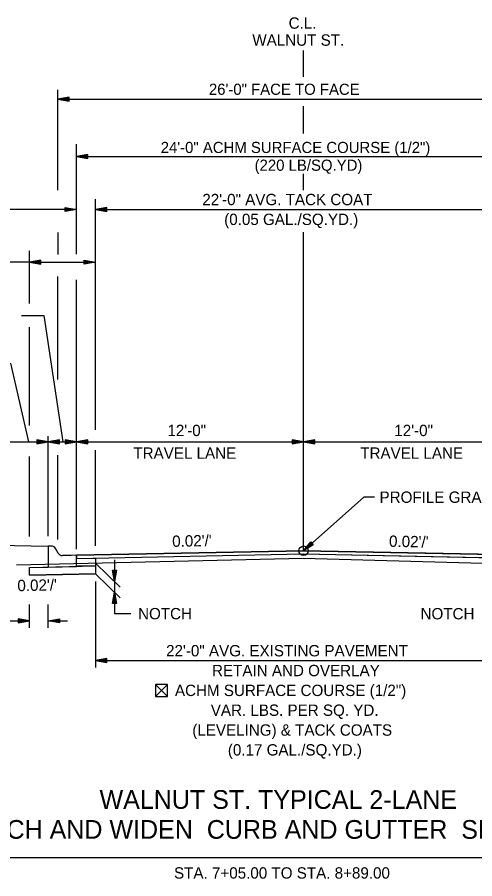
# Model space of a CAD drawing. Extents: x 1001270 to 1003428, y 1840152 to 1842912.
# Drawn here: x 1001337.71 to 1001361.9, y 1840763.76 to 1840809.37 of the extents above; entities that cross this region are included whole.
import ezdxf

# ---------------------------------------------------------------- set-up
doc = ezdxf.new("R2010")
doc.units = 0
doc.layers.add('10', color=7, linetype='Continuous')
doc.layers.add('19', color=7, linetype='Continuous')

msp = doc.modelspace()

# ---------------------------------------------------------------- linework, layer by layer
at = {"layer": '10'}
for p, q in [((1001345.013, 1840774.048), (1001345.654, 1840773.407)), ((1001345.654, 1840774.048), (1001345.013, 1840773.407)), ((1001345.394, 1840773.407), (1001345.405, 1840773.407))]:
    msp.add_line(p, q, dxfattribs=at)
msp.add_lwpolyline([(1001345.405, 1840773.407), (1001345.654, 1840773.407), (1001345.654, 1840774.048), (1001345.013, 1840774.048), (1001345.013, 1840773.407), (1001345.394, 1840773.407)], dxfattribs=at)
at = {"layer": '19'}
for p, q in [((1001352.846, 1840806.222), (1001352.846, 1840807.614)), ((1001339.847, 1840800.22), (1001339.847, 1840805.535)), ((1001340.447, 1840805.137), (1001339.847, 1840805.032)), ((1001339.847, 1840805.032), (1001365.85, 1840805.032)), ((1001339.847, 1840805.032), (1001340.447, 1840804.927)), ((1001340.447, 1840805.082), (1001340.007, 1840805.047)), ((1001340.007, 1840805.017), (1001340.447, 1840804.977)), ((1001340.447, 1840804.927), (1001340.447, 1840805.137)), ((1001352.846, 1840803.218), (1001352.846, 1840804.663)), ((1001340.846, 1840796.831), (1001340.846, 1840802.657)), ((1001341.447, 1840802.11), (1001340.847, 1840802.005)), ((1001341.447, 1840802.055), (1001341.007, 1840802.02)), ((1001341.447, 1840801.9), (1001341.447, 1840802.11)), ((1001340.846, 1840802.005), (1001364.849, 1840802.005)), ((1001340.847, 1840802.005), (1001341.447, 1840801.9)), ((1001341.007, 1840801.99), (1001341.447, 1840801.95)), ((1001352.846, 1840800.214), (1001352.846, 1840801.087)), ((1001340.245, 1840799.094), (1001340.245, 1840799.304)), ((1001340.245, 1840799.304), (1001340.845, 1840799.199)), ((1001341.846, 1840787.532), (1001341.846, 1840799.731)), ((1001342.446, 1840799.304), (1001341.846, 1840799.199)), ((1001342.446, 1840799.094), (1001342.446, 1840799.304)), ((1001340.845, 1840799.199), (1001324.293, 1840799.199)), ((1001340.245, 1840799.249), (1001340.685, 1840799.214)), ((1001340.845, 1840799.199), (1001340.245, 1840799.094)), ((1001340.685, 1840799.184), (1001340.245, 1840799.144)), ((1001340.852, 1840799.198), (1001340.846, 1840799.198)), ((1001341.846, 1840799.199), (1001342.446, 1840799.094)), ((1001341.846, 1840799.199), (1001363.846, 1840799.199)), ((1001342.446, 1840799.249), (1001342.006, 1840799.214)), ((1001342.006, 1840799.184), (1001342.446, 1840799.144)), ((1001339.846, 1840797.981), (1001339.846, 1840796.814)), ((1001352.846, 1840781.126), (1001352.846, 1840797.995)), ((1001338.346, 1840794.208), (1001338.346, 1840796.999)), ((1001338.346, 1840796.399), (1001323.169, 1840796.399)), ((1001338.946, 1840796.504), (1001338.346, 1840796.399)), ((1001338.346, 1840796.399), (1001338.946, 1840796.294)), ((1001338.346, 1840796.399), (1001341.846, 1840796.399)), ((1001338.946, 1840796.449), (1001338.506, 1840796.414)), ((1001338.506, 1840796.384), (1001338.946, 1840796.344)), ((1001338.946, 1840796.294), (1001338.946, 1840796.504)), ((1001341.246, 1840796.294), (1001341.246, 1840796.504)), ((1001341.246, 1840796.504), (1001341.846, 1840796.399)), ((1001341.246, 1840796.449), (1001341.686, 1840796.414)), ((1001341.846, 1840796.399), (1001341.246, 1840796.294)), ((1001341.686, 1840796.384), (1001341.246, 1840796.344)), ((1001339.846, 1840790.194), (1001339.846, 1840795.639)), ((1001340.846, 1840781.214), (1001340.846, 1840795.465)), ((1001337.926, 1840793.587), (1001339.105, 1840793.587)), ((1001339.105, 1840793.587), (1001340.12, 1840786.895)), ((1001338.346, 1840787.749), (1001338.346, 1840792.965)), ((1001337.341, 1840791.052), (1001338.298, 1840786.895)), ((1001338.746, 1840787), (1001338.746, 1840786.79)), ((1001339.346, 1840786.895), (1001338.746, 1840787)), ((1001339.346, 1840781.905), (1001339.346, 1840787.195)), ((1001339.946, 1840787), (1001339.346, 1840786.895)), ((1001339.946, 1840786.79), (1001339.946, 1840787)), ((1001340.246, 1840787), (1001340.246, 1840786.79)), ((1001340.846, 1840786.895), (1001340.246, 1840787)), ((1001341.446, 1840787), (1001340.846, 1840786.895)), ((1001341.446, 1840786.79), (1001341.446, 1840787)), ((1001352.246, 1840787), (1001352.246, 1840786.79)), ((1001352.846, 1840786.895), (1001352.246, 1840787)), ((1001353.446, 1840787), (1001352.846, 1840786.895)), ((1001353.446, 1840786.79), (1001353.446, 1840787)), ((1001331.346, 1840786.895), (1001340.846, 1840786.895)), ((1001339.186, 1840786.91), (1001338.746, 1840786.945)), ((1001338.746, 1840786.79), (1001339.346, 1840786.895)), ((1001338.746, 1840786.84), (1001339.186, 1840786.88)), ((1001339.346, 1840786.895), (1001339.946, 1840786.79)), ((1001339.946, 1840786.945), (1001339.506, 1840786.91)), ((1001339.506, 1840786.88), (1001339.946, 1840786.84)), ((1001340.686, 1840786.91), (1001340.246, 1840786.945)), ((1001340.246, 1840786.79), (1001340.846, 1840786.895)), ((1001340.246, 1840786.84), (1001340.686, 1840786.88)), ((1001340.846, 1840786.895), (1001352.846, 1840786.895)), ((1001340.846, 1840786.895), (1001341.446, 1840786.79)), ((1001341.446, 1840786.945), (1001341.006, 1840786.91)), ((1001341.006, 1840786.88), (1001341.446, 1840786.84)), ((1001352.686, 1840786.91), (1001352.246, 1840786.945)), ((1001352.246, 1840786.79), (1001352.846, 1840786.895)), ((1001352.246, 1840786.84), (1001352.686, 1840786.88)), ((1001352.846, 1840786.895), (1001364.846, 1840786.895)), ((1001352.846, 1840786.895), (1001353.446, 1840786.79)), ((1001353.446, 1840786.945), (1001353.006, 1840786.91)), ((1001353.006, 1840786.88), (1001353.446, 1840786.84)), ((1001338.346, 1840781.88), (1001338.346, 1840786.119)), ((1001339.846, 1840781.717), (1001339.846, 1840786.184)), ((1001341.846, 1840781.391), (1001341.846, 1840786.445)), ((1001352.846, 1840781.126), (1001353.225, 1840781.603)), ((1001352.957, 1840781.239), (1001353.257, 1840781.559)), ((1001353.225, 1840781.603), (1001353.363, 1840781.446)), ((1001336.338, 1840781.432), (1001339.336, 1840781.371)), ((1001339.512, 1840781.371), (1001339.346, 1840781.371)), ((1001339.346, 1840781.371), (1001339.346, 1840781.038)), ((1001339.346, 1840781.038), (1001339.346, 1840780.856)), ((1001339.875, 1840780.996), (1001339.729, 1840781.247)), ((1001340.846, 1840780.886), (1001352.846, 1840781.126)), ((1001353.363, 1840781.446), (1001352.846, 1840781.126)), ((1001352.846, 1840781.126), (1001364.846, 1840780.886)), ((1001353.33, 1840781.478), (1001352.976, 1840781.222)), ((1001339.346, 1840780.856), (1001339.346, 1840780.263)), ((1001340.562, 1840780.881), (1001340.096, 1840780.871)), ((1001340.846, 1840780.886), (1001340.562, 1840780.881)), ((1001340.562, 1840780.881), (1001340.562, 1840780.88)), ((1001340.562, 1840780.88), (1001340.562, 1840780.881)), ((1001340.846, 1840780.72), (1001352.846, 1840780.96)), ((1001340.846, 1840780.72), (1001341.846, 1840780.74)), ((1001340.846, 1840780.303), (1001340.846, 1840780.72)), ((1001341.846, 1840780.74), (1001341.846, 1840779.912)), ((1001341.846, 1840780.74), (1001341.846, 1840780.323)), ((1001352.846, 1840780.96), (1001364.846, 1840780.72)), ((1001338.346, 1840780.243), (1001341.846, 1840780.323)), ((1001338.346, 1840780.243), (1001339.346, 1840780.263)), ((1001338.346, 1840779.836), (1001338.346, 1840780.243)), ((1001338.346, 1840779.836), (1001338.346, 1840780.243)), ((1001338.346, 1840780.243), (1001338.346, 1840780.243)), ((1001339.346, 1840780.263), (1001340.846, 1840780.294)), ((1001340.846, 1840780.303), (1001341.846, 1840780.323)), ((1001341.846, 1840780.323), (1001340.846, 1840780.303)), ((1001340.846, 1840780.303), (1001340.846, 1840780.303)), ((1001341.846, 1840780.474), (1001343.146, 1840779.201)), ((1001341.846, 1840780.323), (1001341.846, 1840779.903)), ((1001338.346, 1840779.836), (1001341.846, 1840779.906)), ((1001341.846, 1840779.903), (1001338.346, 1840779.836)), ((1001341.846, 1840779.906), (1001343.146, 1840778.634)), ((1001342.741, 1840780.095), (1001342.951, 1840780.095)), ((1001342.846, 1840779.495), (1001342.741, 1840780.095)), ((1001342.831, 1840779.655), (1001342.791, 1840780.095)), ((1001342.951, 1840780.095), (1001342.846, 1840779.495)), ((1001342.896, 1840780.095), (1001342.861, 1840779.655)), ((1001341.846, 1840779.505), (1001341.846, 1840774.942)), ((1001342.741, 1840778.327), (1001342.846, 1840778.927)), ((1001342.796, 1840778.327), (1001342.831, 1840778.767)), ((1001342.846, 1840778.927), (1001342.951, 1840778.327)), ((1001342.861, 1840778.767), (1001342.901, 1840778.327)), ((1001342.951, 1840778.327), (1001342.741, 1840778.327)), ((1001338.346, 1840777.037), (1001338.346, 1840778.275)), ((1001339.346, 1840777.037), (1001339.346, 1840778.275)), ((1001336.897, 1840777.415), (1001338.346, 1840777.415)), ((1001336.897, 1840777.415), (1001338.346, 1840777.415)), ((1001337.746, 1840777.52), (1001337.746, 1840777.31)), ((1001338.346, 1840777.415), (1001337.746, 1840777.52)), ((1001337.746, 1840777.52), (1001337.746, 1840777.31)), ((1001338.346, 1840777.415), (1001337.746, 1840777.52)), ((1001338.186, 1840777.43), (1001337.746, 1840777.465)), ((1001338.186, 1840777.43), (1001337.746, 1840777.465)), ((1001337.746, 1840777.31), (1001338.346, 1840777.415)), ((1001337.746, 1840777.31), (1001338.346, 1840777.415)), ((1001337.746, 1840777.36), (1001338.186, 1840777.4)), ((1001337.746, 1840777.36), (1001338.186, 1840777.4)), ((1001339.346, 1840777.415), (1001339.946, 1840777.52)), ((1001339.346, 1840777.415), (1001339.946, 1840777.52)), ((1001339.946, 1840777.31), (1001339.346, 1840777.415)), ((1001339.946, 1840777.31), (1001339.346, 1840777.415)), ((1001339.346, 1840777.415), (1001340.356, 1840777.415)), ((1001339.506, 1840777.43), (1001339.946, 1840777.465)), ((1001339.506, 1840777.43), (1001339.946, 1840777.465)), ((1001339.946, 1840777.36), (1001339.506, 1840777.4)), ((1001339.946, 1840777.36), (1001339.506, 1840777.4)), ((1001339.946, 1840777.52), (1001339.946, 1840777.31)), ((1001339.946, 1840777.52), (1001339.946, 1840777.31)), ((1001342.846, 1840777.809), (1001343.71, 1840777.809)), ((1001342.446, 1840775.415), (1001341.846, 1840775.31)), ((1001341.846, 1840775.31), (1001363.846, 1840775.31)), ((1001341.846, 1840775.31), (1001342.446, 1840775.205)), ((1001342.446, 1840775.36), (1001342.006, 1840775.325)), ((1001342.006, 1840775.295), (1001342.446, 1840775.255)), ((1001342.446, 1840775.205), (1001342.446, 1840775.415)), ((1001334.32, 1840764.885), (1001371.332, 1840764.885)), ((1001337.98, 1840764.885), (1001367.712, 1840764.885))]:
    msp.add_line(p, q, dxfattribs=at)
for points in [[(1001356.607, 1840783.961), (1001356.037, 1840783.961), (1001352.846, 1840781.126)], [(1001337.671, 1840780.372), (1001352.835, 1840780.728), (1001364.846, 1840780.388), (1001369.035, 1840779.851), (1001372.746, 1840778.779), (1001376.583, 1840778.814), (1001379.984, 1840778.819), (1001391.176, 1840779.066)], [(1001340.846, 1840780.294), (1001340.846, 1840780.47), (1001340.846, 1840780.72), (1001340.846, 1840780.886)], [(1001342.846, 1840780.645), (1001342.846, 1840777.809)]]:
    msp.add_lwpolyline(points, dxfattribs=at)
msp.add_lwpolyline([(1001364.846, 1840780.886), (1001352.846, 1840781.126), (1001340.846, 1840780.886), (1001340.846, 1840780.72), (1001352.846, 1840780.96), (1001364.846, 1840780.72)], close=True, dxfattribs=at)
msp.add_circle((1001352.846, 1840781.126), 0.25, dxfattribs=at)
for centre, start, end in [((1001339.512, 1840781.121), 30.1619, 90), ((1001340.091, 1840781.121), 210.1635, 271.1458)]:
    msp.add_arc(centre, 0.25, start, end, dxfattribs=at)

# ---------------------------------------------------------------- texts
for s, height, p in [('C.L.', 0.6, (1001352.058, 1840808.763)), ('WALNUT ST.', 0.6, (1001350.14, 1840807.863)), ('26\'-0" FACE TO FACE', 0.59001, (1001347.843, 1840805.263)), ('24\'-0" ACHM SURFACE COURSE (1/2")', 0.59001, (1001345.293, 1840802.183)), ('(220 LB/SQ.YD)', 0.59001, (1001350.259, 1840801.243)), ('12\'-0"', 0.6, (1001345.648, 1840787.195)), ('12\'-0"', 0.6, (1001357.648, 1840787.195)), ('TRAVEL LANE', 0.6, (1001343.846, 1840785.995)), ('TRAVEL LANE', 0.6, (1001355.846, 1840785.995)), ('NOTCH', 0.6, (1001344.096, 1840777.494)), ('NOTCH', 0.6, (1001359.035, 1840777.491))]:
    msp.add_text(s, height=height, dxfattribs=at).set_placement(p)
for s, height, rotation, p in [('22\'-0" AVG. TACK COAT', 0.6, 360, (1001347.495, 1840799.421)), ('(0.05 GAL./SQ.YD.)', 0.6, 360, (1001348.651, 1840798.371)), ('PROFILE GRADE', 0.6, 360, (1001356.866, 1840783.661)), ("0.02'/'", 0.6, 1.1458, (1001345.906, 1840781.327)), ("0.02'/'", 0.6, 358.8542, (1001357.364, 1840781.336)), ("0.02'/'", 0.6, 1.1458, (1001337.719, 1840778.981)), ('22\'-0" AVG. EXISTING PAVEMENT', 0.6, 360, (1001345.577, 1840775.532)), ('RETAIN AND OVERLAY', 0.6, 360, (1001348.008, 1840774.482)), ('ACHM SURFACE COURSE (1/2")', 0.6, 360, (1001346.047, 1840773.432)), ('VAR. LBS. PER SQ. YD.', 0.6, 360, (1001347.942, 1840772.382)), ('(LEVELING) & TACK COATS', 0.6, 360, (1001346.964, 1840771.332)), ('(0.17 GAL./SQ.YD.)', 0.6, 360, (1001348.844, 1840770.282)), ('WALNUT ST. TYPICAL 2-LANE ', 0.98999, 359.9954, (1001342.058, 1840767.459)), ('NOTCH AND WIDEN  CURB AND GUTTER  SECTION ', 0.98999, 359.9954, (1001334.345, 1840765.876)), ('STA. 7+05.00 TO STA. 8+89.00', 0.6, 359.9954, (1001345.998, 1840763.766))]:
    msp.add_text(s, height=height, rotation=rotation, dxfattribs=at).set_placement(p)

doc.saveas('drawing.dxf')
